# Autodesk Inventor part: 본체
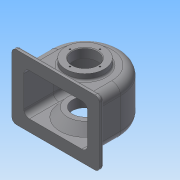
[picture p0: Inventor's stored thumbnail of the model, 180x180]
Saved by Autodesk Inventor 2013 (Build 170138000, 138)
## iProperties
Created: 2015-09
Part Number: 본체
Material: 일반
Document SubType Name: Modeling
Designer: Administrator
Density: 1 g/cm^3
Author: Administrator
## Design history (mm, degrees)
sketch "스케치1"
  geometry: L1 (-57, -47)-(57, -47); L2 (-57, 0)-(-57, -47); L3 (57, 0)-(57, -47); A1 r 57 centre (0, 0) between (57, 0) and (-57, 0); 2 further points
  constraints: 6 end point, 2 point on circle, 2 tangent, 1 centre point, 1 coincident, 1 horizontal, 1 midpoint, 1 parallel, 1 perpendicular, 1 vertical alignment
  dimensions: "d0" = 57 radius of A1; "d1" = 47 distance from line of A1.centre L1
extrude "돌출1" new body sketch "스케치1" distance "d2" = 77; taper "d3" = 0 deg
node "작업 평면1"
sketch "스케치3"
  geometry: L1 (-57, -47)-(-57, 0) reference; L2 (57, 0)-(57, -47) reference; L3 (57, -47)-(-57, -47) reference; L4 (-51, 0)-(-51, -47); L5 (51, 0)-(51, -47); A1 r 57 centre (0, 0) between (57, 0) and (-57, 0) reference; A2 r 51 centre (0, 0) between (51, 0) and (-51, 0); 1 further point
  constraints: 4 end point, 2 point on circle, 2 point on line, 2 tangent, 1 centre point, 1 coincident, 1 parallel, 1 perpendicular
  dimensions: "d20" = 51 radius of A2
extrude "돌출3" cut sketch "스케치3" stored distance "d21" = 67; taper "d22" = 0 deg
node "작업 평면2"
fillet "모깎기5" dims "d24" = 14
fillet "모깎기6" dims "d25" = 9
sketch "스케치4"
  geometry: C1 r 31 at (0, 0); 1 further point
  constraints: 1 centre point, 1 coincident
  dimensions: "d26" = 31 radius of C1
extrude "돌출4" join sketch "스케치4" stored distance "d27" = 67; taper "d28" = 0 deg
sketch "스케치8"
  geometry: L1 (43, 0)-(-47, 0) reference; L2 (-47, 0)-(-47, 5) reference; L3 (-47, 5)-(42, 5) reference; L4 (-31, 77)-(-31, 87) reference; L5 (-31, 87)-(31, 87) reference; L6 (42, 72)-(-47, 72) reference; L7 (-47, 72)-(-47, 77) reference; L8 (-47, 77)-(-31, 77) reference; L9 (57, 63)-(57, 14) reference; L10 (51, 14)-(51, 63) reference; L11 (31, 87)-(31, 77) reference; L12 (31, 77)-(43, 77) reference; L13 (0, 19)-(-28, 19); L14 (-28, 19)-(-43.943, 0); L15 (0, 19)-(0, 0); L16 (0, 0)-(-43.943, 0); A1 r 14 centre (43, 63) between (57, 63) and (43, 77) reference; A2 r 14 centre (43, 14) between (43, 0) and (57, 14) reference; A3 r 9 centre (42, 14) between (42, 5) and (51, 14) reference; A4 r 9 centre (42, 63) between (51, 63) and (42, 72) reference
  constraints: 8 end point, 2 perpendicular, 1 parallel, 1 point on line, 1 vertical alignment
  dimensions: "d50" = 28 distance of L13.start L13.end; "d51" = 68 distance between parallel lines of L13 L5; "d52" = 50 deg angle of L14 L13
revolve "회전3" sketch "스케치8" stored, may be unused: angle "d53" = 90 deg
sketch "스케치10"
  geometry: L1 (57, 63)-(57, 14) reference; L2 (43.918, 0.03)-(43.943, 0) reference; L3 (43.943, 0)-(-47, 0) reference; L4 (-47, 0)-(-47, 5) reference; L5 (-47, 5)-(-39.747, 5) reference; L6 (-39.747, 5)-(-28, 19) reference; L7 (-28, 19)-(28, 19) reference; L8 (28, 19)-(39.747, 5) reference; L9 (39.747, 5)-(42, 5) reference; L10 (51, 14)-(51, 63) reference; L11 (42, 72)-(-47, 72) reference; L12 (-47, 72)-(-47, 77) reference; L13 (-47, 77)-(-31, 77) reference; L14 (-31, 77)-(-31, 87) reference; L15 (-31, 87)-(31, 87) reference; L16 (31, 87)-(31, 77) reference; L17 (31, 77)-(43, 77) reference; L18 (37.416, 0)-(33, 5.263); L19 (0, 0)-(0, 3); L20 (0, 3)-(33, 3); L21 (33, 3)-(33, 5.263); A1 r 14 centre (43, 63) between (57, 63) and (43, 77) reference; A2 r 14 centre (43, 14) between (43.918, 0.03) and (57, 14) reference; A3 r 9 centre (42, 14) between (42, 5) and (51, 14) reference; A4 r 9 centre (42, 63) between (51, 63) and (42, 72) reference
  constraints: 8 end point, 3 perpendicular, 1 parallel, 1 point on line
  dimensions: "d63" = 5 distance between parallel lines of L18 L8; "d65" = 3 distance of L19.start L19.end; "d66" = 33 distance of L19.end L20.end
revolve "회전5" sketch "스케치10" stored, may be unused: angle "d67" = 90 deg
fillet "모깎기7" dims "d68" = 0.5
sketch "스케치11"
  geometry: C1 r 20 at (0, 0); 1 further point
  constraints: 1 centre point, 1 coincident
  dimensions: "d69" = 20 radius of C1
extrude "돌출6" cut sketch "스케치11" stored distance "d70" = 56; taper "d71" = 0 deg
sketch "스케치12"
  geometry: L1 (85, 72)-(1, 72) reference; L2 (-8, 63)-(-8, 14) reference; L3 (1, 5)-(85, 5) reference; L4 (94, 14)-(94, 63) reference; L5 (0, 77)-(86, 77) reference; L6 (100, 63)-(100, 14) reference; L7 (86, 0)-(0, 0) reference; L8 (-14, 14)-(-14, 63) reference; L9 (-27, 90.5)-(113, 90.5); L10 (113, 90.5)-(113, -13.5); L11 (113, -13.5)-(-27, -13.5); L12 (-27, -13.5)-(-27, 90.5); A1 r 9 centre (1, 63) between (1, 72) and (-8, 63) reference; A2 r 9 centre (1, 14) between (-8, 14) and (1, 5) reference; A3 r 9 centre (85, 14) between (85, 5) and (94, 14) reference; A4 r 9 centre (85, 63) between (94, 63) and (85, 72) reference; A5 r 14 centre (0, 63) between (0, 77) and (-14, 63) reference; A6 r 14 centre (86, 63) between (100, 63) and (86, 77) reference; A7 r 14 centre (86, 14) between (86, 0) and (100, 14) reference; A8 r 14 centre (0, 14) between (-14, 14) and (0, 0) reference; 1 further point
  constraints: 8 end point, 2 parallel, 1 horizontal, 1 perpendicular
  dimensions: "d72" = 140 distance of L10.end L11.end; "d73" = 104 distance of L9.end L10.end; "d74" = 13 distance between parallel lines of L8 L12; "d75" = 13.5 distance between parallel lines of L5 L9
extrude "돌출7" join sketch "스케치12" distance "d76" = 7; taper "d77" = 0 deg
fillet "모깎기8" dims "d78" = 7
fillet "모깎기9" dims "d79" = 1
fillet "모깎기10" dims "d80" = 3
sketch "스케치13"
  geometry: L1 (70, -43)-(70, -47) reference; L2 (70, -47)-(51, -47) reference; L3 (51, -47)-(51, 0) reference; L4 (-51, 0)-(-51, -47) reference; L5 (-51, -47)-(-70, -47) reference; L6 (-70, -47)-(-70, -43) reference; L7 (-67, -40)-(-58, -40) reference; L8 (-57, -39)-(-57, 0) reference; L9 (57, 0)-(57, -39) reference; L10 (58, -40)-(67, -40) reference; L11 (42, -47)-(-42, -47) reference; L12 (-6, 63)-(0, 63); L13 (0, 63)-(0, 54.506); L14 (-6, 63)-(-7.498, 54.506); L15 (-7.498, 54.506)-(0, 54.506); A1 r 3 centre (67, -43) between (70, -43) and (67, -40) reference; A2 r 51 centre (0, 0) between (51, 0) and (-51, 0) reference; A3 r 3 centre (-67, -43) between (-67, -40) and (-70, -43) reference; A4 r 1 centre (-58, -39) between (-58, -40) and (-57, -39) reference; A5 r 57 centre (0, 0) between (57, 0) and (-57, 0) reference; A6 r 1 centre (58, -39) between (57, -39) and (58, -40) reference; 2 further points
  constraints: 8 end point, 1 parallel, 1 perpendicular, 1 point on circle, 1 vertical alignment
  dimensions: "d83" = 6 distance of L12.start L12.end; "d84" = 6 distance from line of point (0, 57) L12; "d95" = 100 deg angle of L12 L14; "d96" = 8.49448 distance of L13.end L12.end; "d97" = 7.49781 distance of L14.end L13.end
revolve "회전6" sketch "스케치13" stored, may be unused: angle "d86" = 90 deg
sketch "스케치14"
  geometry: C1 r 6 at (0, 0) reference; 2 further points
  constraints: 1 coincident
hole "구멍1" sketch "스케치14" at (0, 0) diameter "d88" = 4.459; stored, may be unused: countersink angle "d92" = 90 deg, drill point angle "d94" = 118 deg; dims "d89" = 6, "d90" = 4, "d91" = 2, "d93" = 8
fillet "모깎기12" dims "d98" = 3
sketch "스케치15"
  geometry: L1 (69.062, -43)-(69.062, -47) reference; L2 (69.062, -47)-(-69.062, -47) reference; L3 (-69.062, -47)-(-69.062, -43) reference; L4 (-64.936, -40)-(64.936, -40) reference; C1 r 20 at (0, 0) reference; C2 r 31 at (0, 0) reference; 2 further points
  constraints: 1 vertical alignment, 2 other
  dimensions: "d99" = 24 distance of point (0, 0) point (0, 24)
hole "구멍2" sketch "스케치15" at (0, 24) diameter "d100" = 2.459; stored, may be unused: countersink angle "d104" = 90 deg, drill point angle "d106" = 118 deg; dims "d101" = 6, "d102" = 4, "d103" = 2, "d105" = 8
sketch "스케치16"
  geometry: L1 (-67, -40)-(-53.198, -40) reference; L2 (-51.66, -39)-(-51.66, 0) reference; L3 (51.66, 0)-(51.66, -39) reference; L4 (53.198, -40)-(67, -40) reference; L5 (70, -43)-(70, -47) reference; L6 (70, -47)-(-70, -47) reference; L7 (-70, -47)-(-70, -43) reference; C1 r 20 at (0, 0) reference; C2 r 34.899 at (0, 0) reference; C3 r 33 at (0, 0) reference; A1 r 3 centre (-67, -43) between (-67, -40) and (-70, -43) reference; A2 r 51.66 centre (0, 0) between (51.66, 0) and (-51.66, 0) reference; A3 r 3 centre (67, -43) between (70, -43) and (67, -40) reference; 2 further points
  constraints: 1 vertical alignment, 2 other
  dimensions: "d110" = 28 distance of point (0, 0) point (0, 28)
hole "구멍3" sketch "스케치16" at (0, 28) diameter "d111" = 2.459; stored, may be unused: countersink angle "d115" = 90 deg, drill point angle "d117" = 118 deg; dims "d112" = 7, "d113" = 4, "d114" = 2, "d116" = 9
chamfer "모따기1" distance "d121" = 1; stored, may be unused: second distance "d122" = 2, angle "d123" = 45 deg
fillet "모깎기13" dims "d124" = 3
sketch "스케치17"
  geometry: L1 (-14, -9.054)-(-14, -39) reference; L2 (-20.5, -47)-(69.5, -47) reference; 2 further points
  constraints: 1 other
  dimensions: "d125" = 38.5 distance from line of point (24.5, -17) L1; "d126" = 30 distance from line of point (24.5, -17) L2
feature "엠보싱1" sketch "스케치17" dims "d1" = 47, "d127" = 0.5, "d128" = 0
node "솔리드1"
pattern_circular "원형 패턴1" dims angle "d108" = 360 deg
pattern_circular "원형 패턴2" dims angle "d119" = 360 deg
node "절단 모서리 투영2"
node "절단 모서리 투영5"
node "절단 모서리 투영7"
node "절단 모서리 투영8"
node "절단 모서리 투영9"
node "절단 모서리 투영10"
node "절단 모서리 투영11"
node "절단 모서리 투영12"
other parameters: "d13" = 38.5, "d23" = 87
